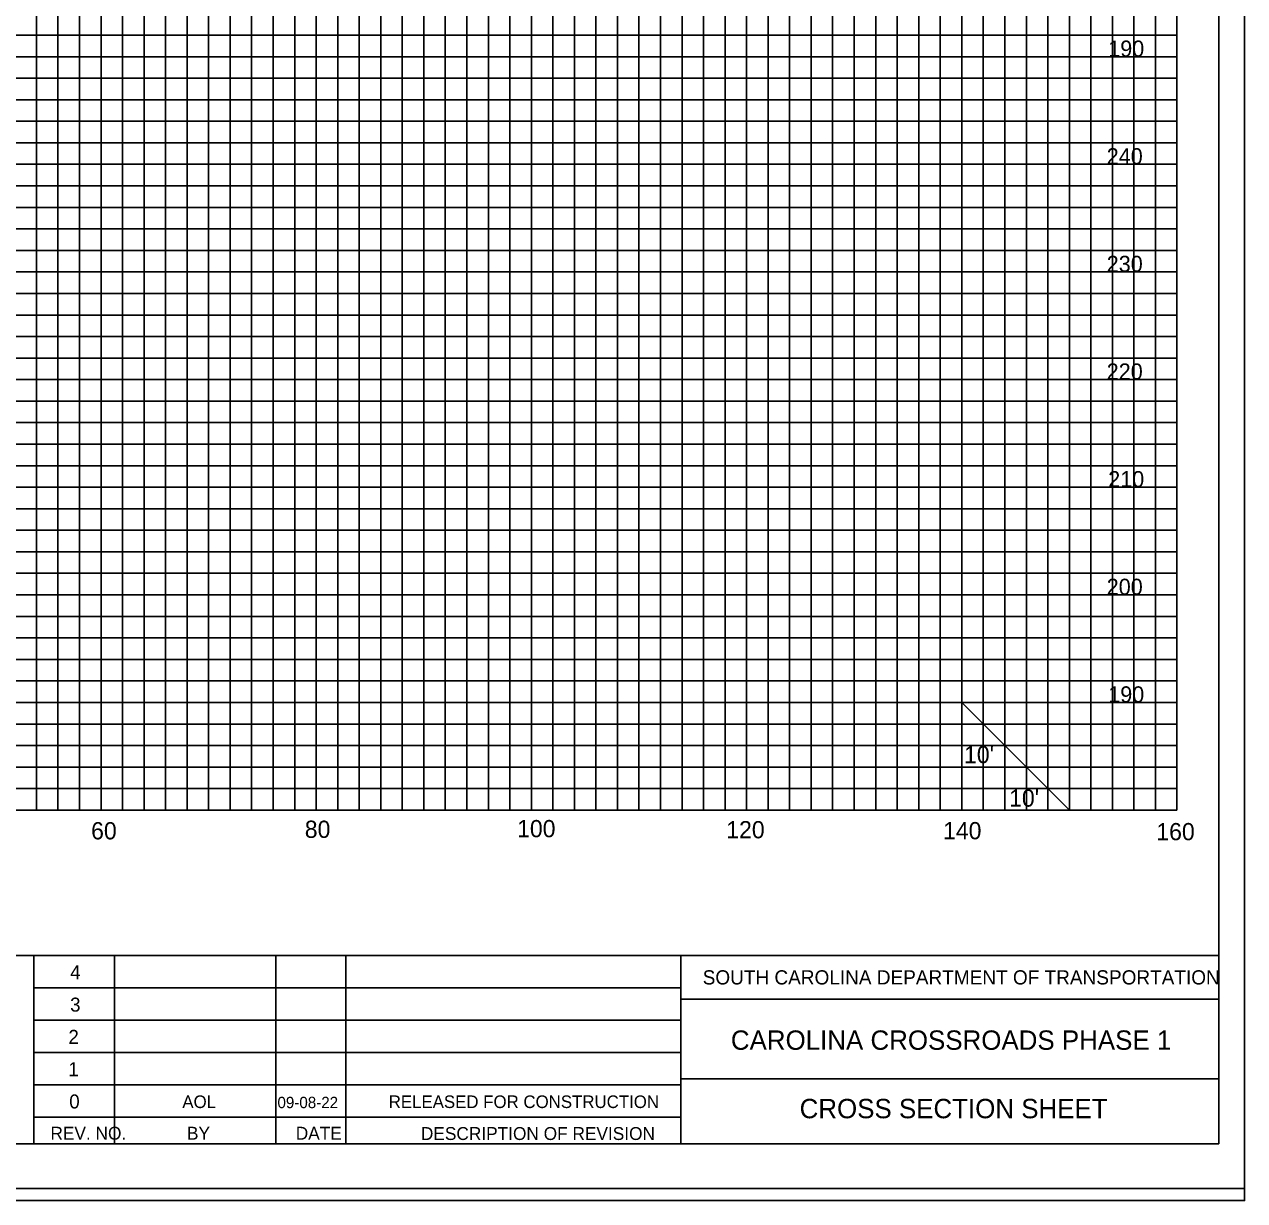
# Model space of a CAD drawing. Extents: x 967 to 1623, y 964 to 7064.
# Drawn here: x 1212.9 to 1326.3, y 3483.7 to 3593 of the extents above; entities that cross this region are included whole.
import ezdxf

# ---------------------------------------------------------------- set-up
doc = ezdxf.new("R2010")
doc.units = 0
for name, color, linetype in [('Default', 7, 'Continuous'), ('RD_SHT_Bndy', 7, 'Continuous'), ('RD_SHT_IplotShp', 7, 'Continuous'), ('RD_SHT_Misc1', 7, 'Continuous'), ('RD_SHT_MjGrid', 7, 'Continuous'), ('RD_SHT_MnGrid', 7, 'Continuous'), ('RD_SHT_TX', 7, 'Continuous'), ('RD_Sketch1', 7, 'Continuous')]:
    doc.layers.add(name, color=color, linetype=linetype)

msp = doc.modelspace()

# ---------------------------------------------------------------- linework, layer by layer
at = {"layer": 'RD_SHT_Bndy'}
for p, q in [((1323.89, 3698.46), (1323.89, 3488.98)), ((996.11, 3506.49), (1323.89, 3506.49)), ((1213.76, 3488.94), (1213.76, 3506.49)), ((1221.26, 3488.95), (1221.26, 3506.48)), ((1236.26, 3488.95), (1236.26, 3506.48)), ((1242.76, 3488.95), (1242.76, 3506.48)), ((1273.88, 3488.98), (1273.88, 3506.49)), ((1213.76, 3503.48), (1273.88, 3503.48)), ((1323.93, 3502.43), (1273.88, 3502.43)), ((1213.76, 3500.48), (1273.88, 3500.48)), ((1213.76, 3497.48), (1273.88, 3497.48)), ((1213.76, 3494.48), (1273.88, 3494.48)), ((1323.89, 3495.04), (1273.88, 3495.04)), ((1213.76, 3491.48), (1273.88, 3491.48)), ((1323.89, 3488.98), (996.11, 3488.98))]:
    msp.add_line(p, q, dxfattribs=at)
at = {"layer": 'RD_SHT_IplotShp'}
for points in [[(967.41, 3483.72), (1326.28, 3483.72), (1326.28, 3703.72), (967.41, 3703.72)], [(988.52, 3484.84), (1326.28, 3484.84), (1326.28, 3702.6), (988.52, 3702.6)]]:
    msp.add_lwpolyline(points, close=True, dxfattribs=at)
at = {"layer": 'RD_SHT_MjGrid'}
for p, q in [((1220, 3520), (1220, 3690)), ((1230, 3520), (1230, 3690)), ((1240, 3520), (1240, 3690)), ((1250, 3520), (1250, 3690)), ((1260, 3520), (1260, 3690)), ((1270, 3520), (1270, 3690)), ((1280, 3520), (1280, 3690)), ((1290, 3520), (1290, 3690)), ((1300, 3520), (1300, 3690)), ((1310, 3520), (1310, 3690)), ((1320, 3520), (1320, 3690)), ((1000, 3590), (1320, 3590)), ((1000, 3580), (1320, 3580)), ((1000, 3570), (1320, 3570)), ((1000, 3560), (1320, 3560)), ((1000, 3550), (1320, 3550)), ((1000, 3540), (1320, 3540)), ((1000, 3530), (1320, 3530)), ((1000, 3520), (1320, 3520))]:
    msp.add_line(p, q, dxfattribs=at)
at = {"layer": 'RD_SHT_MnGrid'}
for p, q in [((1214, 3520), (1214, 3690)), ((1216, 3520), (1216, 3690)), ((1218, 3520), (1218, 3690)), ((1222, 3520), (1222, 3690)), ((1224, 3520), (1224, 3690)), ((1226, 3520), (1226, 3690)), ((1228, 3520), (1228, 3690)), ((1232, 3520), (1232, 3690)), ((1234, 3520), (1234, 3690)), ((1236, 3520), (1236, 3690)), ((1238, 3520), (1238, 3690)), ((1242, 3520), (1242, 3690)), ((1244, 3520), (1244, 3690)), ((1246, 3520), (1246, 3690)), ((1248, 3520), (1248, 3690)), ((1252, 3520), (1252, 3690)), ((1254, 3520), (1254, 3690)), ((1256, 3520), (1256, 3690)), ((1258, 3520), (1258, 3690)), ((1262, 3520), (1262, 3690)), ((1264, 3520), (1264, 3690)), ((1266, 3520), (1266, 3690)), ((1268, 3520), (1268, 3690)), ((1272, 3520), (1272, 3690)), ((1274, 3520), (1274, 3690)), ((1276, 3520), (1276, 3690)), ((1278, 3520), (1278, 3690)), ((1282, 3520), (1282, 3690)), ((1284, 3520), (1284, 3690)), ((1286, 3520), (1286, 3690)), ((1288, 3520), (1288, 3690)), ((1292, 3520), (1292, 3690)), ((1294, 3520), (1294, 3690)), ((1296, 3520), (1296, 3690)), ((1298, 3520), (1298, 3690)), ((1302, 3520), (1302, 3690)), ((1304, 3520), (1304, 3690)), ((1306, 3520), (1306, 3690)), ((1308, 3520), (1308, 3690)), ((1312, 3520), (1312, 3690)), ((1314, 3520), (1314, 3690)), ((1316, 3520), (1316, 3690)), ((1318, 3520), (1318, 3690)), ((1000, 3592), (1320, 3592)), ((1000, 3588), (1320, 3588)), ((1000, 3586), (1320, 3586)), ((1000, 3584), (1320, 3584)), ((1000, 3582), (1320, 3582)), ((1000, 3578), (1320, 3578)), ((1000, 3576), (1320, 3576)), ((1000, 3574), (1320, 3574)), ((1000, 3572), (1320, 3572)), ((1000, 3568), (1320, 3568)), ((1000, 3566), (1320, 3566)), ((1000, 3564), (1320, 3564)), ((1000, 3562), (1320, 3562)), ((1000, 3558), (1320, 3558)), ((1000, 3556), (1320, 3556)), ((1000, 3554), (1320, 3554)), ((1000, 3552), (1320, 3552)), ((1000, 3548), (1320, 3548)), ((1000, 3546), (1320, 3546)), ((1000, 3544), (1320, 3544)), ((1000, 3542), (1320, 3542)), ((1000, 3538), (1320, 3538)), ((1000, 3536), (1320, 3536)), ((1000, 3534), (1320, 3534)), ((1000, 3532), (1320, 3532)), ((1000, 3528), (1320, 3528)), ((1000, 3526), (1320, 3526)), ((1000, 3524), (1320, 3524)), ((1000, 3522), (1320, 3522))]:
    msp.add_line(p, q, dxfattribs=at)
at = {"layer": 'RD_SHT_TX'}
msp.add_line((1300, 3530), (1310, 3520), dxfattribs=at)
at = {"layer": 'RD_Sketch1'}
msp.add_lwpolyline([(967.41, 3483.72), (1326.28, 3483.72), (1326.28, 3703.72), (967.41, 3703.72)], close=True, dxfattribs=at)

# ---------------------------------------------------------------- texts
at = {"layer": 'Default'}
for s, p in [('190', (1313.61, 3590)), ('240', (1313.47, 3580)), ('230', (1313.47, 3570)), ('220', (1313.47, 3560)), ('210', (1313.61, 3550)), ('200', (1313.47, 3540)), ('190', (1313.61, 3530))]:
    msp.add_text(s, height=1.5, dxfattribs=at).set_placement(p)
at = {"layer": 'RD_SHT_Misc1'}
for s, height, p in [('AOL', 1.17, (1227.56, 3492.32)), ('09-08-22', 1.053, (1236.4, 3492.31)), ('RELEASED FOR CONSTRUCTION', 1.17, (1246.74, 3492.32))]:
    msp.add_text(s, height=height, dxfattribs=at).set_placement(p)
at = {"layer": 'RD_SHT_TX'}
for s, height, p in [("10'", 1.6, (1300.21, 3524.36)), ("10'", 1.6, (1304.4, 3520.32)), ('80', 1.6, (1238.94, 3517.42)), ('100', 1.6, (1258.67, 3517.48)), ('120', 1.6, (1278.11, 3517.38)), ('60', 1.6, (1219.08, 3517.28)), ('140', 1.6, (1298.26, 3517.29)), ('160', 1.6, (1318.08, 3517.2)), ('4', 1.3, (1217.13, 3504.28)), ('SOUTH CAROLINA DEPARTMENT OF TRANSPORTATION', 1.32, (1275.92, 3503.8)), ('3', 1.3, (1217.13, 3501.28)), ('2', 1.3, (1216.97, 3498.28)), ('1', 1.3, (1216.97, 3495.28)), ('0', 1.3, (1217.05, 3492.28)), ('REV. NO.', 1.2, (1215.3, 3489.38)), ('BY', 1.2, (1227.99, 3489.38)), ('DATE', 1.2, (1238.1, 3489.38)), ('DESCRIPTION OF REVISION', 1.2, (1249.73, 3489.35))]:
    msp.add_text(s, height=height, dxfattribs=at).set_placement(p)
for s, p in [('CAROLINA CROSSROADS PHASE 1', (1278.54, 3497.73)), ('CROSS SECTION SHEET', (1284.93, 3491.37))]:
    msp.add_text(s, height=1.8, rotation=0, dxfattribs=at).set_placement(p)

doc.saveas('drawing.dxf')
